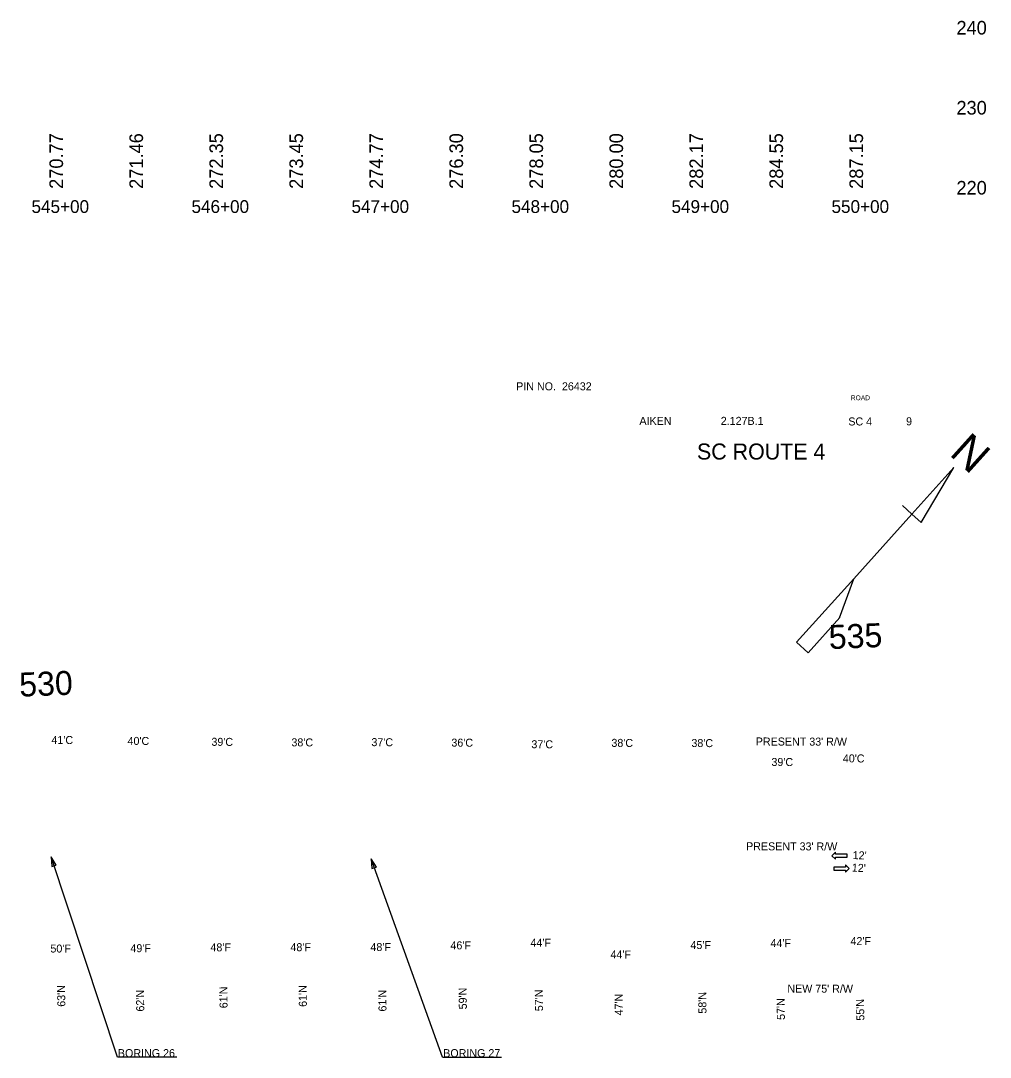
# Model space of a CAD drawing. Extents: x 49105 to 50775, y 45514 to 53458.
# Drawn here: x 50160 to 50766, y 49586 to 50234 of the extents above; entities that cross this region are included whole.
import ezdxf

# ---------------------------------------------------------------- set-up
doc = ezdxf.new("R2010")
doc.units = 0
for name, color, linetype in [('Level 1', 7, 'Continuous'), ('Level 14', 7, 'Continuous'), ('Level 19', 7, 'Continuous'), ('Level 2', 7, 'Continuous'), ('Level 20', 7, 'Continuous'), ('Level 24', 7, 'Continuous'), ('Level 29', 7, 'Continuous'), ('Level 33', 7, 'Continuous'), ('Level 42', 7, 'Continuous'), ('Level 43', 7, 'Continuous'), ('Level 48', 7, 'Continuous')]:
    doc.layers.add(name, color=color, linetype=linetype)

msp = doc.modelspace()

# ---------------------------------------------------------------- linework, layer by layer
at = {"layer": 'Level 14'}
for points in [[(50676.36, 49711.32), (50676.35, 49713.24), (50669.02, 49713.21), (50669.01, 49714.51), (50666.76, 49712.24), (50669.03, 49709.99), (50669.02, 49711.29)], [(50667.96, 49705.14), (50667.96, 49703.22), (50675.3, 49703.24), (50675.3, 49701.94), (50677.56, 49704.21), (50675.29, 49706.47), (50675.29, 49705.16)]]:
    msp.add_lwpolyline(points, close=True, dxfattribs=at)
at = {"layer": 'Level 2'}
for p, q in [((50743.06, 49954.85), (50716.83, 49925.71)), ((50722.66, 49920.47), (50743.06, 49954.85)), ((50743.06, 49954.85), (50743.06, 49954.85)), ((50680.43, 49885.29), (50716.83, 49925.71)), ((50711, 49930.96), (50716.83, 49925.71)), ((50716.83, 49925.71), (50722.66, 49920.47)), ((50722.66, 49920.47), (50722.97, 49920.81)), ((50680.43, 49885.29), (50644.7, 49845.6)), ((50671.65, 49860.89), (50680.43, 49885.29)), ((50651.98, 49839.04), (50671.83, 49861.09)), ((50671.83, 49861.09), (50671.65, 49860.89)), ((50644.7, 49845.6), (50651.98, 49839.04))]:
    msp.add_line(p, q, dxfattribs=at)
at = {"layer": 'Level 24'}
for p, q in [((50178.76, 49711.57), (50179.22, 49705.4)), ((50182.07, 49706.35), (50178.76, 49711.57)), ((50179.22, 49705.4), (50182.07, 49706.35)), ((50378.75, 49710.29), (50379.37, 49704.14)), ((50382.2, 49705.15), (50378.75, 49710.29)), ((50379.37, 49704.14), (50382.2, 49705.15))]:
    msp.add_line(p, q, dxfattribs=at)
at = {"layer": 'Level 29'}
for p, q in [((50220.33, 49586.27), (50178.76, 49711.57)), ((50423.45, 49586.27), (50378.75, 49710.29)), ((50257.39, 49586.27), (50220.33, 49586.27)), ((50423.45, 49586.27), (50460.24, 49586.27))]:
    msp.add_line(p, q, dxfattribs=at)

# ---------------------------------------------------------------- texts
at = {"layer": 'Level 1'}
for p in [(50619.23, 49781.1), (50613.17, 49715.62)]:
    msp.add_text("PRESENT 33' R/W ", height=5, rotation=359.87225, dxfattribs=at).set_placement(p)
for s, p in [('BORING 26', (50220.56, 49586.35)), ('BORING 27', (50423.88, 49586.35))]:
    msp.add_text(s, height=5, dxfattribs=at).set_placement(p)
at = {"layer": 'Level 19'}
for s, rotation, p in [('535', 2.37987, (50665.16, 49841.29)), ('530', 2.20467, (50159.16, 49811.58))]:
    msp.add_text(s, height=15, rotation=rotation, dxfattribs=at).set_placement(p)
at = {"layer": 'Level 2'}
msp.add_text('N', height=20, rotation=318, dxfattribs=at).set_placement((50739.68, 49962.88))
at = {"layer": 'Level 20'}
for p in [(50679.7, 49710.15), (50679.19, 49702.3)]:
    msp.add_text("12'", height=5, rotation=357.85007, dxfattribs=at).set_placement(p)
at = {"layer": 'Level 24'}
for s, height, p in [('PIN NO.  26432', 5, (50469.47, 50003.04)), ('ROAD', 3, (50678.66, 49996.86)), ('AIKEN', 5, (50546.51, 49981.45)), (' 2.127B.1', 5, (50595.49, 49981.45)), ('SC 4', 5, (50677.06, 49981.07)), ('9', 5, (50713.17, 49981.16)), ('SC ROUTE 4', 10, (50582.48, 49959.79))]:
    msp.add_text(s, height=height, dxfattribs=at).set_placement(p)
at = {"layer": 'Level 33'}
msp.add_text("NEW 75' R/W", height=5, rotation=359.78111, dxfattribs=at).set_placement((50638.95, 49626.72))
at = {"layer": 'Level 42'}
for s, height, p in [('240', 8.5, (50744.65, 50225.35)), ('230', 8.5, (50744.65, 50175.35)), ('220', 8.5, (50744.65, 50125.35)), ('545+00', 8, (50166.55, 50113.85)), ('545+00', 8, (50166.55, 50113.85)), ('546+00', 8, (50266.55, 50113.85)), ('547+00', 8, (50366.55, 50113.85)), ('548+00', 8, (50466.55, 50113.85)), ('549+00', 8, (50566.55, 50113.85)), ('550+00', 8, (50666.55, 50113.85))]:
    msp.add_text(s, height=height, dxfattribs=at).set_placement(p)
at = {"layer": 'Level 43'}
for s, p in [('270.77', (50186.28, 50128.93)), ('271.46', (50236.28, 50128.93)), ('272.35', (50286.28, 50128.93)), ('273.45', (50336.28, 50128.93)), ('274.77', (50386.28, 50128.93)), ('276.30', (50436.28, 50128.93)), ('278.05', (50486.28, 50128.93)), ('280.00', (50536.28, 50128.93)), ('282.17', (50586.28, 50128.93)), ('284.55', (50636.28, 50128.93)), ('287.15', (50686.28, 50128.93))]:
    msp.add_text(s, height=8.5, rotation=90, dxfattribs=at).set_placement(p)
at = {"layer": 'Level 48'}
for s, rotation, p in [("41'C", 359.63336, (50179.01, 49782.08)), ("40'C", 359.63336, (50226.57, 49781.5)), ("39'C", 359.63339, (50279, 49780.9)), ("38'C", 359.63339, (50329, 49780.59)), ("37'C", 359.63336, (50378.99, 49780.69)), ("36'C", 359.63336, (50428.98, 49780.41)), ("37'C", 359.63336, (50478.99, 49779.39)), ("38'C", 359.63339, (50528.99, 49780.24)), ("38'C", 359.63339, (50578.99, 49780.14)), ("39'C", 359.63336, (50629, 49768.32)), ("40'C", 359.63336, (50673.64, 49770.56)), ("44'F", 359.63336, (50478.4, 49655.38)), ("44'F", 359.63339, (50628.4, 49655.13)), ("42'F", 359.63339, (50678.41, 49656.41)), ("50'F", 359.63339, (50178.37, 49651.74)), ("49'F", 359.63336, (50228.37, 49651.96)), ("48'F", 359.63336, (50278.38, 49652.51)), ("48'F", 359.63336, (50328.38, 49652.59)), ("48'F", 359.63339, (50378.38, 49652.67)), ("46'F", 359.63339, (50428.39, 49653.73)), ("45'F", 359.63336, (50578.39, 49653.94)), ("44'F", 359.63336, (50528.4, 49648.04)), ("63'N", 90.85283, (50187.73, 49617.87)), ("62'N", 90.85283, (50237.05, 49614.87)), ("61'N", 90.85283, (50289.13, 49616.93)), ("61'N", 90.85283, (50338.68, 49617.8)), ("61'N", 90.85283, (50388.44, 49614.88)), ("59'N", 90.85283, (50438.67, 49616.24)), ("57'N", 90.85283, (50486.29, 49615.08)), ("47'N", 90.85283, (50536.18, 49612.43)), ("58'N", 90.85283, (50588.44, 49613.56)), ("57'N", 90.85283, (50637.46, 49609.66)), ("55'N", 90.85283, (50687.1, 49609.19))]:
    msp.add_text(s, height=5, rotation=rotation, dxfattribs=at).set_placement(p)

doc.saveas('drawing.dxf')
